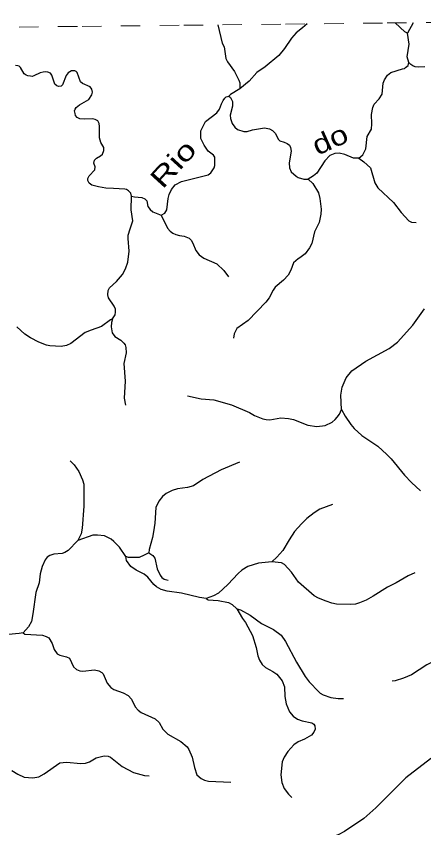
# Model space of a CAD drawing. Extents: x 320.3 to 346.3, y 7455.4 to 7483.3.
# Drawn here: x 328.871 to 330.97, y 7479.04 to 7483.215 of the extents above; entities that cross this region are included whole.
import ezdxf
from ezdxf.enums import TextEntityAlignment as Align

# ---------------------------------------------------------------- set-up
doc = ezdxf.new("R2010")
doc.units = 0
doc.header["$LTSCALE"] = 0.032
doc.linetypes.add('SHORT_DASHED', pattern=[2.7, 1.5, -1.2])
doc.layers.add('53', color=7, linetype='SHORT_DASHED', lineweight=13)
doc.layers.add('7', color=7, linetype='Continuous', lineweight=25)
doc.layers.add('61', color=7, linetype='Continuous')

msp = doc.modelspace()

# ---------------------------------------------------------------- linework, layer by layer
at = {"layer": '53'}
msp.add_lwpolyline([(325.5417, 7483.1214), (326.0657, 7483.1274), (326.5897, 7483.1334), (327.1137, 7483.1394), (327.6377, 7483.1453), (328.1617, 7483.1513), (328.6857, 7483.1572), (329.2097, 7483.1631), (329.7337, 7483.1689), (330.2577, 7483.1748), (330.7817, 7483.1806), (331.3057, 7483.1864), (331.8297, 7483.1923), (332.3537, 7483.198), (332.8777, 7483.2038), (333.4017, 7483.2096), (333.9256, 7483.2153)], dxfattribs=at)
at = {"layer": '7'}
msp.add_line((330.916, 7483.1821), (330.886, 7483.1286), dxfattribs=at)
for points in [[(330.37, 7483.1761), (330.3449, 7483.156), (330.3127, 7483.1302), (330.289, 7483.103), (330.2527, 7483.0499), (330.2227, 7483.0134), (330.1529, 7482.9552), (330.1102, 7482.926), (330.071, 7482.8818), (330.0227, 7482.8411)], [(330.886, 7483.1286), (330.8731, 7483.1347), (330.8232, 7483.1811)], [(329.9093, 7483.1709), (329.9323, 7483.0765), (329.9412, 7483.0584), (329.9503, 7482.9984), (329.9589, 7482.9814), (329.9948, 7482.9303), (330.0182, 7482.8858), (330.0226, 7482.8718), (330.0227, 7482.8411)], [(330.8932, 7482.9772), (330.8839, 7483.0062), (330.8946, 7483.0714), (330.886, 7483.1286)], [(330.6359, 7482.4847), (330.6568, 7482.5025), (330.6711, 7482.5324), (330.6791, 7482.5963), (330.7008, 7482.6335), (330.7032, 7482.6623), (330.701, 7482.7096), (330.7072, 7482.7458), (330.7151, 7482.7631), (330.7402, 7482.7901), (330.7548, 7482.8145), (330.7614, 7482.8708), (330.7672, 7482.8884), (330.7831, 7482.912), (330.8001, 7482.9259), (330.8598, 7482.945), (330.8699, 7482.9468), (330.8761, 7482.9513), (330.8898, 7482.9619), (330.8932, 7482.9772)], [(330.9762, 7482.9541), (330.9436, 7482.9529), (330.925, 7482.9556), (330.9132, 7482.9608), (330.904, 7482.9667), (330.8932, 7482.9772)], [(329.4647, 7482.2903), (329.4603, 7482.3046), (329.449, 7482.3176), (329.4392, 7482.3232), (329.4304, 7482.3258), (329.3726, 7482.329), (329.3326, 7482.3315), (329.295, 7482.3373), (329.261, 7482.3457), (329.247, 7482.3559), (329.2394, 7482.3697), (329.2391, 7482.3798), (329.2473, 7482.3943), (329.2752, 7482.4248), (329.2767, 7482.4404), (329.271, 7482.4597), (329.2733, 7482.4756), (329.2835, 7482.4854), (329.3046, 7482.4976), (329.3153, 7482.5051), (329.3216, 7482.5244), (329.3224, 7482.5395), (329.3067, 7482.5656), (329.2995, 7482.5901), (329.3, 7482.6474), (329.2987, 7482.6631), (329.2908, 7482.6765), (329.2777, 7482.6847), (329.2634, 7482.6874), (329.2215, 7482.6854), (329.1989, 7482.688), (329.1849, 7482.695), (329.1764, 7482.7047), (329.1739, 7482.7143), (329.1718, 7482.728), (329.1745, 7482.7379), (329.1794, 7482.7452), (329.1969, 7482.7597), (329.208, 7482.7659), (329.2445, 7482.7864), (329.2597, 7482.8101), (329.263, 7482.8249), (329.2607, 7482.8403), (329.251, 7482.8526), (329.2127, 7482.8696), (329.2019, 7482.8783), (329.1844, 7482.926), (329.1803, 7482.9316), (329.1721, 7482.9342), (329.1555, 7482.9337), (329.1387, 7482.9235), (329.1287, 7482.9103), (329.1091, 7482.8622), (329.1025, 7482.8562), (329.0889, 7482.8546), (329.0801, 7482.8571), (329.0692, 7482.8666), (329.055, 7482.9126), (329.0482, 7482.9221), (329.0342, 7482.9272), (329.0216, 7482.9287), (329.0092, 7482.9275), (328.9934, 7482.9235), (328.9619, 7482.9087), (328.9535, 7482.9056), (328.9441, 7482.9065), (328.9307, 7482.9091), (328.9221, 7482.9114), (328.9124, 7482.919), (328.8935, 7482.9518), (328.8855, 7482.9582), (328.8784, 7482.9601), (328.8679, 7482.9612)], [(329.8941, 7482.4907), (329.8868, 7482.5007), (329.8594, 7482.5216), (329.838, 7482.5513), (329.8218, 7482.5855), (329.8208, 7482.6264), (329.8462, 7482.6732), (329.9041, 7482.7186), (329.9179, 7482.737), (329.9279, 7482.7647), (329.9368, 7482.7809), (329.9451, 7482.7936), (329.9524, 7482.7999), (329.9651, 7482.8039)], [(330.0227, 7482.8411), (329.9737, 7482.812), (329.9651, 7482.8039)], [(329.9651, 7482.8039), (329.9739, 7482.7975), (329.9789, 7482.7866), (329.984, 7482.7764), (329.9852, 7482.7641), (329.9853, 7482.7528), (329.9732, 7482.7068), (329.9741, 7482.6885), (329.9833, 7482.663), (329.9964, 7482.6439), (330.0112, 7482.6317), (330.0424, 7482.6229), (330.0598, 7482.6226), (330.0878, 7482.6315), (330.1494, 7482.6419), (330.1745, 7482.6362), (330.191, 7482.6277), (330.2048, 7482.6135), (330.2217, 7482.5819), (330.2291, 7482.5743), (330.2515, 7482.5679), (330.2662, 7482.5602), (330.2775, 7482.5517), (330.2843, 7482.5394), (330.287, 7482.5216), (330.2762, 7482.4615), (330.279, 7482.4345), (330.2867, 7482.4145), (330.3122, 7482.3916), (330.3227, 7482.3858), (330.3518, 7482.3776), (330.3747, 7482.3769)], [(330.6359, 7482.4847), (330.6088, 7482.4851), (330.5631, 7482.5045), (330.5349, 7482.5111), (330.5125, 7482.5085), (330.4855, 7482.4982), (330.4597, 7482.4718), (330.4186, 7482.4073), (330.4024, 7482.3936), (330.3747, 7482.3769)], [(329.7979, 7482.3837), (329.8599, 7482.4001), (329.8739, 7482.4096), (329.8899, 7482.4354), (329.894, 7482.4465), (329.8941, 7482.4907)], [(330.6359, 7482.4847), (330.6619, 7482.4667), (330.6953, 7482.4348), (330.7185, 7482.359), (330.7331, 7482.3318), (330.8137, 7482.2575), (330.8536, 7482.2048), (330.8933, 7482.1633), (330.9063, 7482.1566), (330.9311, 7482.1533)], [(329.617, 7482.1924), (329.6354, 7482.2028), (329.6458, 7482.2198), (329.6535, 7482.2784), (329.6588, 7482.2981), (329.6705, 7482.3247), (329.6897, 7482.3487), (329.7224, 7482.3643), (329.7979, 7482.3837)], [(330.3747, 7482.3769), (330.3978, 7482.3548), (330.4279, 7482.3062), (330.4346, 7482.2777), (330.4411, 7482.2235), (330.4402, 7482.1975), (330.4304, 7482.1543), (330.4072, 7482.1065), (330.3931, 7482.0468), (330.3811, 7482.023), (330.3589, 7481.9929), (330.3323, 7481.9721), (330.3222, 7481.9678), (330.2994, 7481.9474), (330.2853, 7481.9082), (330.2721, 7481.8831), (330.248, 7481.8578), (330.2048, 7481.8214), (330.1937, 7481.8056), (330.1728, 7481.7657), (330.157, 7481.7441), (330.0655, 7481.6504), (330.0069, 7481.6082), (329.9928, 7481.582), (329.9906, 7481.5596)], [(329.3663, 7481.6582), (329.3797, 7481.6797), (329.3822, 7481.6934), (329.382, 7481.7077), (329.3753, 7481.7236), (329.3454, 7481.7662), (329.3425, 7481.7827), (329.3448, 7481.8042), (329.3505, 7481.8184), (329.3866, 7481.8513), (329.4179, 7481.8873), (329.4336, 7481.9158), (329.4451, 7481.9505), (329.4532, 7482.0069), (329.4479, 7482.0722), (329.4482, 7482.0891), (329.4569, 7482.1216), (329.4713, 7482.1631), (329.4629, 7482.219), (329.4647, 7482.2903)], [(329.4647, 7482.2903), (329.4792, 7482.2856), (329.5179, 7482.2831), (329.5338, 7482.2763), (329.5427, 7482.2649), (329.5487, 7482.2365), (329.5604, 7482.2213), (329.5736, 7482.2098), (329.617, 7482.1924)], [(329.617, 7482.1924), (329.6494, 7482.1255), (329.6633, 7482.1103), (329.6771, 7482.0993), (329.6936, 7482.0918), (329.712, 7482.0869), (329.7358, 7482.0845), (329.761, 7482.0738), (329.7715, 7482.0631), (329.7806, 7482.0475), (329.7963, 7482.0101), (329.8138, 7481.9881), (329.8379, 7481.9712), (329.9036, 7481.9407), (329.9407, 7481.9078), (329.9641, 7481.8749)], [(330.5462, 7481.1927), (330.5425, 7481.265), (330.5503, 7481.3067), (330.571, 7481.3542), (330.5993, 7481.3911), (330.6707, 7481.4413), (330.7909, 7481.5056), (330.8353, 7481.5391), (330.9141, 7481.6263), (330.9729, 7481.7095)], [(329.3663, 7481.6582), (329.356, 7481.6536), (329.3106, 7481.6186), (329.2564, 7481.5993), (329.2265, 7481.5876), (329.1528, 7481.5321), (329.1305, 7481.5212), (329.1015, 7481.5156), (329.0437, 7481.5187), (329.0267, 7481.5236), (328.988, 7481.5385), (328.9448, 7481.5613), (328.9154, 7481.5803), (328.8748, 7481.6175)], [(329.3663, 7481.6582), (329.3611, 7481.6395), (329.3598, 7481.6171), (329.3652, 7481.5867), (329.3791, 7481.567), (329.4088, 7481.5481), (329.4257, 7481.5334), (329.4322, 7481.5245), (329.4362, 7481.5102), (329.4366, 7481.4838), (329.4258, 7481.4283), (329.4316, 7481.3383), (329.4275, 7481.2501), (329.4339, 7481.2136)], [(329.7533, 7481.2627), (329.8238, 7481.2477), (329.8882, 7481.241), (329.9788, 7481.2163), (330.0716, 7481.1764), (330.0981, 7481.1603), (330.1405, 7481.1442), (330.1585, 7481.1402), (330.1775, 7481.1391), (330.2341, 7481.1487), (330.2727, 7481.145), (330.2986, 7481.1398), (330.3735, 7481.1119), (330.4196, 7481.105), (330.462, 7481.1089), (330.4976, 7481.127), (330.5137, 7481.1397), (330.5247, 7481.1521), (330.5359, 7481.1688), (330.5462, 7481.1927)], [(330.5462, 7481.1927), (330.5644, 7481.1584), (330.5941, 7481.1143), (330.6111, 7481.0949), (330.6503, 7481.0575), (330.7325, 7481.0025), (330.7792, 7480.9608), (330.8023, 7480.9375), (330.8709, 7480.8536), (330.9061, 7480.817), (330.9537, 7480.7743)], [(329.1483, 7480.9272), (329.1689, 7480.907), (329.1941, 7480.8724), (329.2129, 7480.8303), (329.2182, 7480.8083), (329.2189, 7480.6955), (329.2097, 7480.5811), (329.205, 7480.5523), (329.188, 7480.5174)], [(330.0204, 7480.9208), (329.9269, 7480.8819), (329.8321, 7480.8313), (329.7833, 7480.7995), (329.7534, 7480.7907), (329.7017, 7480.7835), (329.6732, 7480.776), (329.6423, 7480.7596), (329.6247, 7480.7443), (329.6046, 7480.7198), (329.5905, 7480.6884), (329.5849, 7480.608), (329.5784, 7480.5626), (329.5734, 7480.534), (329.5548, 7480.4714), (329.5537, 7480.455)], [(330.4999, 7480.7027), (330.4346, 7480.6785), (330.4057, 7480.661), (330.3674, 7480.6304), (330.34, 7480.6032), (330.3044, 7480.5643), (330.2772, 7480.5214), (330.2436, 7480.4658), (330.2135, 7480.4316), (330.1869, 7480.409)], [(329.4347, 7480.4364), (329.4021, 7480.4843), (329.3744, 7480.5134), (329.3596, 7480.5256), (329.3258, 7480.5413), (329.289, 7480.5462), (329.2649, 7480.5446), (329.188, 7480.5174)], [(329.188, 7480.5174), (329.1377, 7480.4674), (329.1215, 7480.4563), (329.1078, 7480.4513), (329.0653, 7480.4471), (329.0439, 7480.4408), (329.0309, 7480.4319), (329.0201, 7480.4191), (329.0049, 7480.3845), (328.9949, 7480.3465), (328.9886, 7480.2998), (328.9726, 7480.2506), (328.9564, 7480.1402), (328.9487, 7480.1019), (328.9348, 7480.0735), (328.9062, 7480.0425)], [(329.5537, 7480.455), (329.53, 7480.442), (329.5036, 7480.4303), (329.4775, 7480.4307), (329.4499, 7480.4307), (329.4347, 7480.4364)], [(329.8486, 7480.2196), (329.8153, 7480.2249), (329.7214, 7480.2474), (329.6479, 7480.2572), (329.618, 7480.2653), (329.594, 7480.2801), (329.5788, 7480.292), (329.5486, 7480.3286), (329.529, 7480.3442), (329.4884, 7480.365), (329.4613, 7480.3847), (329.4382, 7480.4145), (329.4347, 7480.4364)], [(329.5537, 7480.455), (329.5747, 7480.4411), (329.5845, 7480.427), (329.5969, 7480.3714), (329.6114, 7480.3401), (329.6211, 7480.3281), (329.6334, 7480.3197), (329.6527, 7480.3133)], [(330.1869, 7480.409), (330.1194, 7480.4006), (330.0639, 7480.3841), (330.032, 7480.3647), (330.0132, 7480.3488), (329.9608, 7480.2922), (329.9122, 7480.2474), (329.8874, 7480.2329), (329.8486, 7480.2196)], [(330.9231, 7480.3512), (330.89, 7480.3366), (330.8278, 7480.3007), (330.7826, 7480.2785), (330.7099, 7480.2311), (330.6735, 7480.2116), (330.6386, 7480.1973), (330.6181, 7480.1912), (330.5927, 7480.1883), (330.52, 7480.1905), (330.4958, 7480.1952), (330.4669, 7480.2057), (330.4283, 7480.221), (330.4056, 7480.2335), (330.324, 7480.304), (330.2883, 7480.3558), (330.2528, 7480.3946), (330.2373, 7480.4034), (330.1869, 7480.409)], [(329.8486, 7480.2196), (329.86, 7480.2125), (329.9107, 7480.2099), (329.9645, 7480.1986), (329.9823, 7480.188), (330.0066, 7480.1673)], [(330.0066, 7480.1673), (330.0268, 7480.1608), (330.0757, 7480.1343), (330.1342, 7480.0917), (330.196, 7480.06), (330.2359, 7480.0312), (330.2583, 7479.9992), (330.3152, 7479.8916), (330.3595, 7479.8191), (330.3798, 7479.7914), (330.4287, 7479.7393), (330.437, 7479.7319), (330.4512, 7479.7247), (330.4906, 7479.7109), (330.5294, 7479.7045), (330.5562, 7479.7051)], [(330.0066, 7480.1673), (330.0356, 7480.1175), (330.0516, 7480.0959), (330.087, 7480.0288), (330.1058, 7479.9677), (330.1145, 7479.9248), (330.1231, 7479.9028), (330.1379, 7479.8806), (330.1547, 7479.8648), (330.1931, 7479.8441), (330.2128, 7479.8296), (330.2414, 7479.7956), (330.2526, 7479.7648), (330.2548, 7479.715), (330.261, 7479.6777), (330.2791, 7479.6373), (330.2967, 7479.615), (330.3193, 7479.5995), (330.344, 7479.5894), (330.3933, 7479.5793), (330.4036, 7479.5735), (330.4096, 7479.5642), (330.4099, 7479.5479), (330.4029, 7479.5323), (330.3908, 7479.5168), (330.3558, 7479.496), (330.3233, 7479.4818), (330.3009, 7479.4665), (330.2691, 7479.4316), (330.2506, 7479.4039), (330.2402, 7479.3791), (330.2335, 7479.3126), (330.2382, 7479.2729), (330.2509, 7479.242), (330.2731, 7479.213), (330.2907, 7479.1959)], [(328.9062, 7480.0425), (328.886, 7480.0391), (328.8315, 7480.0351), (328.8038, 7480.0272), (328.788, 7480.0181), (328.7573, 7479.9865), (328.7374, 7479.971), (328.686, 7479.9534), (328.6663, 7479.942), (328.6136, 7479.8859), (328.5653, 7479.8559), (328.5522, 7479.8447), (328.534, 7479.818), (328.5176, 7479.7809), (328.5027, 7479.7674), (328.466, 7479.7437), (328.4415, 7479.7009), (328.4265, 7479.6859), (328.4007, 7479.6654), (328.3827, 7479.658), (328.3512, 7479.6515), (328.3415, 7479.6451)], [(328.9062, 7480.0425), (328.9155, 7480.0357), (329.0059, 7480.0305), (329.0243, 7480.0241), (329.0384, 7480.0168), (329.0563, 7479.9879), (329.0657, 7479.9572), (329.082, 7479.9354), (329.0948, 7479.9282), (329.1294, 7479.919), (329.1444, 7479.9118), (329.1656, 7479.8688), (329.1813, 7479.8545), (329.1987, 7479.8478), (329.2146, 7479.8457), (329.2742, 7479.8526), (329.296, 7479.8473), (329.3113, 7479.8384), (329.3189, 7479.8312), (329.3386, 7479.7836), (329.3582, 7479.7619), (329.3739, 7479.7515), (329.4216, 7479.734), (329.4472, 7479.7199), (329.464, 7479.7009), (329.4842, 7479.6614), (329.4983, 7479.6444), (329.514, 7479.6333), (329.5866, 7479.6006), (329.6064, 7479.5813), (329.6257, 7479.5467), (329.6517, 7479.5209), (329.7184, 7479.4836), (329.7507, 7479.4568), (329.7604, 7479.4423), (329.7777, 7479.4034), (329.789, 7479.3504), (329.8008, 7479.3127), (329.8231, 7479.293), (329.8404, 7479.2846), (329.8609, 7479.2804), (329.9754, 7479.2755)], [(331.3345, 7479.939), (331.3321, 7479.921), (331.3062, 7479.8423), (331.267, 7479.7766), (331.2129, 7479.6574), (331.1436, 7479.5398), (331.0749, 7479.4599), (331.0041, 7479.3943), (330.8778, 7479.2962), (330.7232, 7479.1426), (330.6617, 7479.0873), (330.5618, 7479.0211), (330.529, 7479.0038), (330.4669, 7478.9821), (330.4066, 7478.9561)], [(331.3345, 7479.939), (331.3083, 7479.9197), (331.2757, 7479.9053), (331.2601, 7479.9016), (331.2131, 7479.9017), (331.1297, 7479.917), (331.1092, 7479.9185), (331.0779, 7479.9143), (331.0472, 7479.9086), (330.9854, 7479.8786), (330.907, 7479.8272), (330.866, 7479.8095), (330.823, 7479.7956), (330.8072, 7479.7936)], [(328.8482, 7479.3347), (328.8789, 7479.315), (328.9113, 7479.3006), (328.9563, 7479.2967), (328.9865, 7479.3027), (329.0148, 7479.3176), (329.0962, 7479.3742), (329.1291, 7479.3784), (329.2044, 7479.3708), (329.2276, 7479.3719), (329.2486, 7479.3785), (329.2827, 7479.4005), (329.3233, 7479.4097), (329.3437, 7479.4083), (329.3566, 7479.4031), (329.4172, 7479.3555), (329.4746, 7479.3243), (329.532, 7479.3087), (329.5554, 7479.3077)]]:
    msp.add_lwpolyline(points, dxfattribs=at)

# ---------------------------------------------------------------- texts
at = {"layer": '61'}
for s, rotation, width, p in [('do', 24.2, 1.25, (330.5072, 7482.5354)), ('Rio', 47.699, 1.35, (329.7161, 7482.4221))]:
    msp.add_text(s, height=0.1, rotation=rotation, dxfattribs=dict(at, width=width)).set_placement(p, align=Align.CENTER)

doc.saveas('drawing.dxf')
